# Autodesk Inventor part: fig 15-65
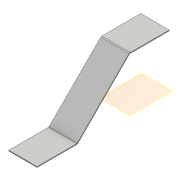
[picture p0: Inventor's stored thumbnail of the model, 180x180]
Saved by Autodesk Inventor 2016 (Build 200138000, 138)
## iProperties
Created: 2015-07
Part Number: fig 15-65
Material: Generic
Document SubType Name: Sheet Metal
Designer: Sandeep
Density: 1 g/cm^3
Sheet Metal Rule: Default_mm
Appearance: Default
Author: Sandeep
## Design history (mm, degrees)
sketch "Sketch1"
  geometry: L1 (0, 0)-(16.327, 0); L2 (16.327, 0)-(16.327, 22.261); L3 (16.327, 22.261)-(0, 22.261); L4 (0, 22.261)-(0, 0)
  constraints: 8 end point, 2 parallel, 1 horizontal, 1 perpendicular
workplane "Work Plane1"
sketch "Sketch2"
  geometry: L1 (0, -53.275)-(16.202, -53.275); L2 (16.202, -53.275)-(16.202, -30.325); L3 (16.202, -30.325)-(0, -30.325); L4 (0, -30.325)-(0, -53.275); 1 further point
  constraints: 8 end point, 2 parallel, 1 horizontal, 1 perpendicular
node "Face1"
node "Face2"
bend "Bend2" dims "d7" = 0.5 (= BendReliefWidth), "d8" = 0.25 (= BendReliefDepth), "d9" = 1 (= MinimumRemnant), "d10" = 0.5 (= BendRadius), "d11" = 0.5 (= BendRadius), "SeamGap" = 0.01, "Thickness" = 0.5
body "Solid1"
face "Plate1" dims "Thickness" = 0.5
face "Plate2" dims "d2" = 0.5 (= BendRadius), "d3" = 0.5 (= BendReliefWidth), "d5" = 1 (= MinimumRemnant), "Thickness" = 0.5
bend "Bend1" dims "d2" = 0.5 (= BendRadius), "d3" = 0.5 (= BendReliefWidth), "d4" = 0.25 (= BendReliefDepth), "d5" = 1 (= MinimumRemnant), "d6" = 0.5 (= BendRadius), "SeamGap" = 0.01, "Thickness" = 0.5
other parameters: "BendRadius" = 0.5 (= Thickness), "BendReliefWidth" = 0.5 (= Thickness), "BendReliefDepth" = 0.25 (= 0.5 x Thickness), "CornerReliefSize" = 2 (= 4 x Thickness), "MinimumRemnant" = 1 (= 2 x Thickness), "TransitionRadius" = 0.5 (= BendRadius), "JacobiRadiusSize" = 0.5 (= BendRadius), "GapSize" = 0.5 (= Thickness), "d1" = 0.5 (= BendRadius)
